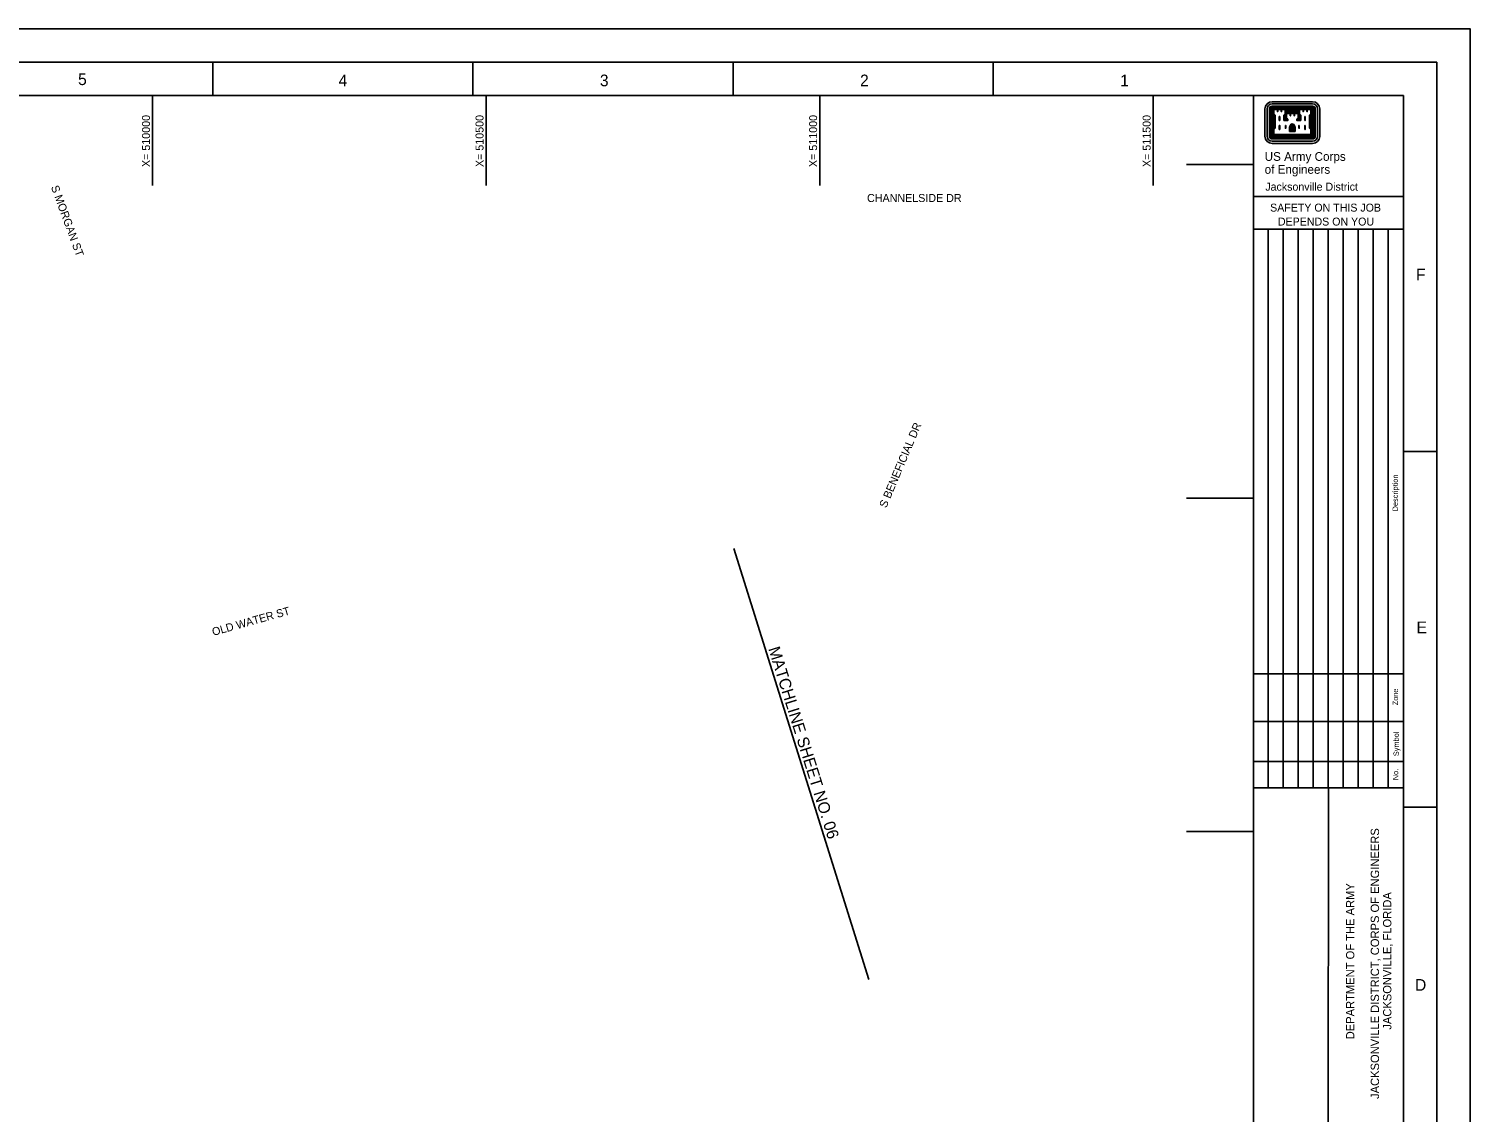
# Model space of a CAD drawing. Extents: x 507575 to 511975, y 1309304 to 1312704.
# Drawn here: x 509814 to 511975, y 1311079 to 1312704 of the extents above; entities that cross this region are included whole.
import ezdxf

# ---------------------------------------------------------------- set-up
doc = ezdxf.new("R2010")
doc.units = 0
for name, color, linetype in [('G-ANNO-NPLT', 7, 'Continuous'), ('G-ANNO-TEXT-LOGO', 7, 'Continuous'), ('G-ANNO-TEXT-TTLB', 7, 'Continuous'), ('G-ANNO-TTLB', 7, 'Continuous'), ('V-ANNO-MATC', 7, 'Continuous'), ('V-ANNO-MATC-IDEN', 7, 'Continuous'), ('V-ROAD-IDEN', 7, 'Continuous'), ('V-TOPO-COOR-STAT', 7, 'Continuous')]:
    doc.layers.add(name, color=color, linetype=linetype)

msp = doc.modelspace()

# ---------------------------------------------------------------- linework, layer by layer
at = {"layer": 'G-ANNO-NPLT'}
msp.add_lwpolyline([(507575, 1312703.6), (511975, 1312703.6), (511975, 1309303.7), (507575, 1309303.7)], close=True, dxfattribs=at)
msp.add_lwpolyline([(511975, 1312653.6), (511975, 1312703.6), (511925, 1312703.6)], dxfattribs=at)
at = {"layer": 'G-ANNO-TEXT-LOGO'}
for p, q in [((511667.3, 1312583.6), (511667.3, 1312542.6)), ((511670.5, 1312542.6), (511670.5, 1312583.6)), ((511674, 1312583.6), (511674, 1312542.6)), ((511674.9, 1312583.6), (511674.9, 1312542.6)), ((511675.7, 1312583.6), (511675.7, 1312542.6)), ((511676.6, 1312583.6), (511676.6, 1312542.6)), ((511677.5, 1312583.6), (511677.5, 1312542.6)), ((511738.8, 1312594.3), (511678, 1312594.3)), ((511678, 1312591.1), (511738.8, 1312591.1)), ((511738.8, 1312587.7), (511678, 1312587.7)), ((511738.8, 1312586.8), (511678, 1312586.8)), ((511738.8, 1312585.9), (511678, 1312585.9)), ((511738.8, 1312585.1), (511678, 1312585.1)), ((511738.8, 1312584.2), (511678, 1312584.2)), ((511678.4, 1312583.6), (511678.4, 1312542.9)), ((511679.2, 1312583.6), (511679.2, 1312543.8)), ((511679.9, 1312574.9), (511679.9, 1312553.9)), ((511680.8, 1312574), (511680.8, 1312554.9)), ((511699.1, 1312583.4), (511717.7, 1312583.4)), ((511699.1, 1312582.5), (511717.7, 1312582.5)), ((511699.1, 1312581.7), (511717.7, 1312581.7)), ((511699.1, 1312580.8), (511717.7, 1312580.8)), ((511699.1, 1312579.9), (511717.7, 1312579.9)), ((511699.1, 1312579.1), (511717.7, 1312579.1)), ((511699.1, 1312578.2), (511717.7, 1312578.2)), ((511736, 1312574), (511736, 1312554.9)), ((511736.9, 1312574.8), (511736.9, 1312554)), ((511737.6, 1312583.6), (511737.6, 1312543.8)), ((511738.4, 1312583.6), (511738.4, 1312542.9)), ((511739.3, 1312583.6), (511739.3, 1312542.6)), ((511740.2, 1312583.6), (511740.2, 1312542.6)), ((511741, 1312583.6), (511741, 1312542.6)), ((511741.9, 1312583.6), (511741.9, 1312542.6)), ((511742.8, 1312583.6), (511742.8, 1312542.6)), ((511746.2, 1312583.6), (511746.2, 1312542.6)), ((511749.5, 1312542.6), (511749.5, 1312583.6)), ((511704.4, 1312549.7), (511704.4, 1312556.4)), ((511705.2, 1312549.7), (511705.2, 1312556.4)), ((511706.1, 1312549.7), (511706.1, 1312556.4)), ((511707, 1312549.7), (511707, 1312556.4)), ((511707.8, 1312549.7), (511707.8, 1312556.4)), ((511709, 1312549.7), (511709, 1312556.4)), ((511709.8, 1312549.7), (511709.8, 1312556.4)), ((511710.7, 1312549.7), (511710.7, 1312556.4)), ((511711.6, 1312549.7), (511711.6, 1312556.4)), ((511712.4, 1312549.7), (511712.4, 1312556.4)), ((511738.8, 1312542), (511678, 1312542)), ((511738.8, 1312541.2), (511678, 1312541.2)), ((511738.8, 1312540.3), (511678, 1312540.3)), ((511738.8, 1312539.4), (511678, 1312539.4)), ((511738.8, 1312538.6), (511678, 1312538.6)), ((511738.8, 1312535.1), (511678, 1312535.1)), ((511678, 1312531.8), (511738.8, 1312531.8)), ((511738.4, 1312542.9), (511678.4, 1312542.9)), ((511737.6, 1312543.8), (511679.2, 1312543.8)), ((511704.4, 1312549.7), (511712.4, 1312549.7))]:
    msp.add_line(p, q, dxfattribs=at)
for points in [[(511679.9, 1312583.6), (511679.9, 1312575.7), (511681.6, 1312574), (511681.6, 1312554.9), (511679.9, 1312553.1), (511679.9, 1312544.4), (511736.9, 1312544.4), (511736.9, 1312553.1), (511735.1, 1312554.9), (511735.1, 1312574), (511736.9, 1312575.7), (511736.9, 1312583.6), (511729.4, 1312583.6), (511723.6, 1312583.6), (511718.2, 1312583.6), (511718.2, 1312575.7), (511720.1, 1312574), (511720.1, 1312567), (511715.9, 1312567), (511715.9, 1312567.7), (511717.7, 1312569.5), (511717.7, 1312577.3), (511710.2, 1312577.3), (511704.4, 1312577.3), (511699.1, 1312577.3), (511699.1, 1312569.5), (511700.9, 1312567.7), (511700.9, 1312567), (511696.7, 1312567), (511696.7, 1312574), (511698.5, 1312575.7), (511698.5, 1312583.6), (511691, 1312583.6), (511685.2, 1312583.6), (511679.9, 1312583.6)], [(511680.7, 1312582.7), (511680.7, 1312576.1), (511682.5, 1312574.3), (511682.5, 1312554.5), (511680.7, 1312552.7), (511680.7, 1312545.3), (511736.1, 1312545.3), (511736.1, 1312552.7), (511734.2, 1312554.5), (511734.2, 1312574.3), (511736.1, 1312576.1), (511736.1, 1312582.7), (511730.7, 1312582.7), (511730.7, 1312579.6), (511730.2, 1312579.6), (511730.2, 1312582.7), (511724.9, 1312582.7), (511724.9, 1312579.6), (511724.5, 1312579.6), (511724.5, 1312582.7), (511719.1, 1312582.7), (511719.1, 1312576.1), (511720.9, 1312574.3), (511720.9, 1312566.2), (511715.1, 1312566.2), (511715.1, 1312568.1), (511716.9, 1312569.9), (511716.9, 1312576.5), (511711.5, 1312576.5), (511711.5, 1312573.4), (511711.1, 1312573.4), (511711.1, 1312576.5), (511705.7, 1312576.5), (511705.7, 1312573.4), (511705.2, 1312573.4), (511705.2, 1312576.5), (511699.9, 1312576.5), (511699.9, 1312569.9), (511701.7, 1312568.1), (511701.7, 1312566.2), (511695.9, 1312566.2), (511695.9, 1312574.3), (511697.7, 1312576.1), (511697.7, 1312582.7), (511692.4, 1312582.7), (511692.4, 1312579.6), (511691.9, 1312579.6), (511691.9, 1312582.7), (511686.5, 1312582.7), (511686.5, 1312579.6), (511686.1, 1312579.6), (511686.1, 1312582.7), (511680.7, 1312582.7)], [(511698.1, 1312574.1), (511697.6, 1312573.6), (511697.6, 1312567.9), (511699.5, 1312567.9), (511698.2, 1312569.2), (511698.2, 1312574.2)], [(511718.7, 1312574.1), (511719.2, 1312573.6), (511719.2, 1312567.9), (511717.4, 1312567.9), (511718.6, 1312569.2), (511718.6, 1312574.2)], [(511688.9, 1312572), (511688.9, 1312566.2), (511689.5, 1312566.2), (511689.5, 1312572), (511688.9, 1312572)], [(511688.9, 1312558.7), (511688.9, 1312552.8), (511689.5, 1312552.8), (511689.5, 1312558.7), (511688.9, 1312558.7)], [(511698.1, 1312558.7), (511698.1, 1312554.6), (511698.6, 1312554.6), (511698.6, 1312558.7), (511698.1, 1312558.7)], [(511718.7, 1312558.7), (511718.7, 1312554.6), (511718.2, 1312554.6), (511718.2, 1312558.7), (511718.7, 1312558.7)], [(511727.8, 1312572), (511727.8, 1312566.2), (511727.3, 1312566.2), (511727.3, 1312572), (511727.8, 1312572)], [(511727.8, 1312558.7), (511727.8, 1312552.8), (511727.3, 1312552.8), (511727.3, 1312558.7), (511727.8, 1312558.7)]]:
    msp.add_lwpolyline(points, dxfattribs=at)
for centre, major_axis, start_param, end_param in [((511678.1, 1312583.6), (10.7, 0), 1.57078, 3.141576), ((511678.1, 1312583.6), (7.49, 0), 1.57078, 3.141576), ((511678.1, 1312583.6), (4.02, 0), 1.57078, 3.141576), ((511678.1, 1312583.6), (3.15, 0), 1.57078, 3.141576), ((511678.1, 1312583.6), (2.28, 0), 1.57078, 3.141576), ((511678.1, 1312583.6), (1.41, 0), 1.57078, 3.141576), ((511678.1, 1312583.6), (0.546, 0), 1.57078, 3.141576), ((511738.8, 1312583.6), (10.7, 0), 6.283169, 7.853965), ((511738.8, 1312583.6), (7.49, 0), 6.28317, 7.853966), ((511738.8, 1312583.6), (4.02, 0), 6.283169, 7.853965), ((511738.8, 1312583.6), (3.15, 0), 6.283169, 7.853965), ((511738.8, 1312583.6), (2.28, 0), 6.283169, 7.853965), ((511738.8, 1312583.6), (1.41, 0), 6.283169, 7.853965), ((511738.8, 1312583.6), (0.546, 0), 6.283169, 7.853965), ((511709.9, 1312555.9), (-5.55, 0), 4.985832, 6.214359), ((511709.9, 1312555.9), (-4.69, 0), 4.947465, 6.21436), ((511709.9, 1312555.9), (-3.82, 0), 4.947465, 6.21436), ((511709.9, 1312555.9), (-2.95, 0), 4.947465, 6.21436), ((511706.9, 1312555.9), (2.08, 0), 0.068794, 1.335689), ((511706.9, 1312555.9), (2.95, 0), 0.068794, 1.335689), ((511706.9, 1312555.9), (3.82, 0), 0.068795, 1.335689), ((511709.9, 1312555.9), (-2.08, 0), 4.947465, 6.214359), ((511706.9, 1312555.9), (4.69, 0), 0.068795, 1.335689), ((511706.9, 1312555.9), (5.55, 0), 0.068795, 1.29842), ((511678.1, 1312542.5), (-10.7, 0), 6.28317, 7.853966), ((511678.1, 1312542.5), (-7.49, 0), 6.28317, 7.853966), ((511678.1, 1312542.5), (-4.02, 0), 6.28317, 7.853966), ((511678.1, 1312542.5), (-3.15, 0), 6.28317, 7.853966), ((511678.1, 1312542.5), (-2.28, 0), 6.28317, 7.853966), ((511678.1, 1312542.5), (-1.41, 0), 6.28317, 7.853966), ((511678.1, 1312542.5), (-0.546, 0), 6.28317, 7.853966), ((511738.8, 1312542.5), (4.02, 0), 4.712373, 6.28317), ((511738.8, 1312542.5), (3.15, 0), 4.712373, 6.28317), ((511738.8, 1312542.5), (2.28, 0), 4.712373, 6.28317), ((511738.8, 1312542.5), (1.41, 0), 4.712373, 6.28317), ((511738.8, 1312542.5), (0.546, 0), 4.712373, 6.28317), ((511738.8, 1312542.5), (10.7, 0), 4.712373, 6.28317), ((511738.8, 1312542.5), (-7.49, 0), 1.570781, 3.141577)]:
    msp.add_ellipse(centre, major_axis=major_axis, ratio=0.99964, start_param=start_param, end_param=end_param, dxfattribs=at)
at = {"layer": 'G-ANNO-TTLB'}
for p, q in [((510090, 1312653.6), (510090, 1312603.6)), ((510480, 1312653.6), (510480, 1312603.6)), ((510870, 1312653.6), (510870, 1312603.6)), ((511260, 1312653.6), (511260, 1312603.6)), ((511650, 1312603.6), (511650, 1309403.7)), ((511650, 1312452.4), (511875, 1312452.4)), ((511649.4, 1312403.3), (511874.4, 1312403.3)), ((511672.3, 1312403.3), (511672.3, 1311565.4)), ((511694.8, 1312403.3), (511694.8, 1311565.4)), ((511717.3, 1312403.3), (511717.3, 1311565.4)), ((511739.8, 1312403.3), (511739.8, 1311565.4)), ((511762.3, 1312403.3), (511762.3, 1311565.4)), ((511784.8, 1312403.3), (511784.8, 1311565.4)), ((511807.3, 1312403.3), (511807.3, 1311565.4)), ((511829.8, 1312403.3), (511829.8, 1311565.4)), ((511852.3, 1312403.3), (511852.3, 1311565.4)), ((511925, 1312070.1), (511875, 1312070.1)), ((511650, 1311736.4), (511875, 1311736.4)), ((511650, 1311665.2), (511875, 1311665.2)), ((511650, 1311605.2), (511875, 1311605.2)), ((511650, 1311565.4), (511875, 1311565.4)), ((511761.8, 1310705.8), (511762.5, 1311565.4)), ((511762.5, 1311565.4), (511762.5, 1311530)), ((511925, 1311536.8), (511875, 1311536.8))]:
    msp.add_line(p, q, dxfattribs=at)
for points in [[(507625, 1309353.7), (511925, 1309353.7), (511925, 1312653.6), (507625, 1312653.6)], [(511875, 1312603.6), (507750, 1312603.6), (507750, 1309403.7), (511875, 1309403.7)]]:
    msp.add_lwpolyline(points, close=True, dxfattribs=at)
at = {"layer": 'V-ANNO-MATC'}
msp.add_line((510871, 1311924.7), (511073.6, 1311278.1), dxfattribs=at)
at = {"layer": 'V-TOPO-COOR-STAT'}
for p, q in [((510000, 1312468.6), (510000, 1312603.6)), ((510500, 1312468.6), (510500, 1312603.6)), ((511000, 1312468.6), (511000, 1312603.6)), ((511500, 1312468.6), (511500, 1312603.6)), ((511650, 1312500), (511550, 1312500)), ((511650, 1312000), (511550, 1312000)), ((511650, 1311500), (511550, 1311500))]:
    msp.add_line(p, q, dxfattribs=at)

# ---------------------------------------------------------------- texts
at = {"layer": 'G-ANNO-TEXT-TTLB'}
for s, height, p in [('US Army Corps', 13.086, (511666.9, 1312505.7)), ('of Engineers', 13.086, (511666.9, 1312486.3)), ('Jacksonville District', 11.9, (511667.9, 1312461)), ('SAFETY ON THIS JOB', 11.9, (511675.1, 1312429.6)), ('DEPENDS ON YOU', 11.9, (511686.8, 1312408.7))]:
    msp.add_text(s, height=height, dxfattribs=at).set_placement(p)
for s, height, p in [('Description', 8, (511866.6, 1311980.1)), ('Zone', 8, (511866.9, 1311689.4)), ('Symbol', 8, (511868.1, 1311613.1)), ('No.', 8, (511867.1, 1311577)), ('JACKSONVILLE DISTRICT, CORPS OF ENGINEERS', 12.5, (511838.4, 1311099.2)), ('DEPARTMENT OF THE ARMY', 12.5, (511801.4, 1311188.6)), ('JACKSONVILLE, FLORIDA', 12.5, (511856.9, 1311203))]:
    msp.add_text(s, height=height, rotation=90, dxfattribs=at).set_placement(p)
at = {"layer": 'G-ANNO-TTLB'}
for s, p in [('5', (509888.2, 1312619.3)), ('4', (510278.7, 1312617.5)), ('3', (510670.4, 1312617.5)), ('2', (511060.4, 1312617.5)), ('1', (511450.4, 1312617.5)), ('F', (511893.8, 1312326.3)), ('E', (511894.6, 1311797.5)), ('D', (511892.3, 1311261.4))]:
    msp.add_text(s, height=17.5, dxfattribs=at).set_placement(p)
at = {"layer": 'V-ANNO-MATC-IDEN'}
msp.add_text('MATCHLINE SHEET NO. 06', height=17.52, rotation=287.3937, dxfattribs=at).set_placement((510922.7, 1311774.3))
at = {"layer": 'V-ROAD-IDEN'}
for s, rotation, p in [('S MORGAN ST', 290.118, (509847.3, 1312466.4)), ('S BENEFICIAL DR', 67.1625, (511099.7, 1311984.4)), ('OLD WATER ST', 15.6236, (510090.9, 1311793.4))]:
    msp.add_text(s, height=12, rotation=rotation, dxfattribs=at).set_placement(p)
msp.add_text('CHANNELSIDE DR', height=12, dxfattribs=at).set_placement((511070.9, 1312444))
at = {"layer": 'V-TOPO-COOR-STAT'}
for s, p in [('X= 510000', (509996, 1312496.4)), ('X= 510500', (510496, 1312496.4)), ('X= 511000', (510996, 1312496.4)), ('X= 511500', (511496, 1312496.4))]:
    msp.add_text(s, height=12, rotation=90, dxfattribs=at).set_placement(p)

doc.saveas('drawing.dxf')
